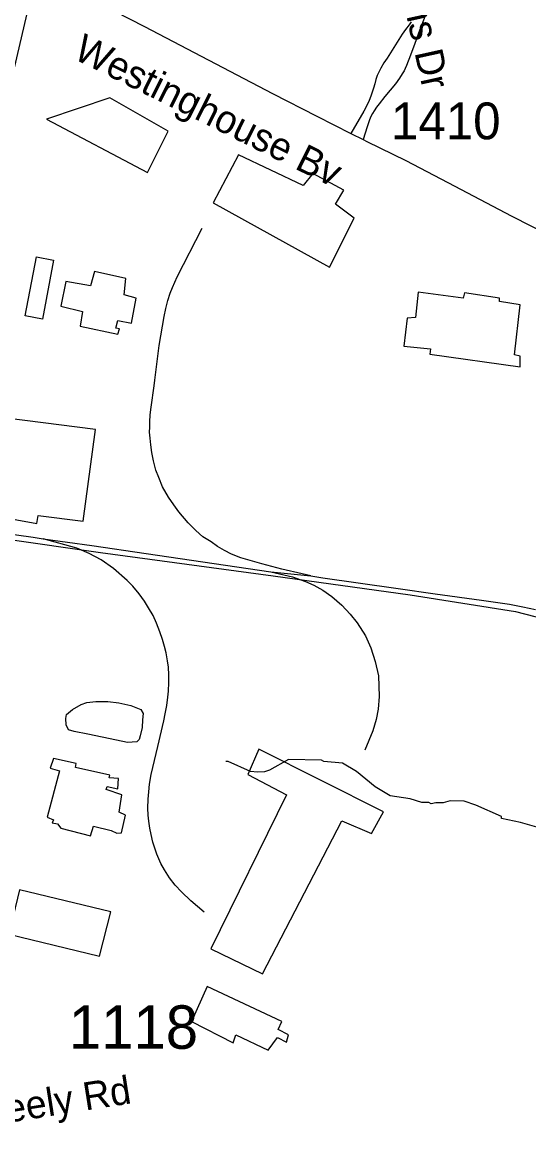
# Model space of a CAD drawing. Extents: x 1383679 to 1536984, y 460658 to 651027.
# Drawn here: x 1408689 to 1410408, y 506502 to 510300 of the extents above; entities that cross this region are included whole.
import ezdxf

# ---------------------------------------------------------------- set-up
doc = ezdxf.new("R2010")
doc.units = 0
for name, color, linetype in [('Exist Cultural Warehouse Building Footprint', 7, 'Continuous'), ('Exist Hydrographic Misc Water Feature', 7, 'Continuous'), ('Exist Railroad Mainline', 7, 'Continuous'), ('Exist Railroad Spur', 7, 'Continuous'), ('Exist Road Non-System Secondary Historical Number Label', 7, 'Continuous'), ('Exist Road Non-System Type 51', 7, 'Continuous'), ('Exist Road Non-System Type 51 Label', 7, 'Continuous'), ('Exist Road Primary NC Attributed', 7, 'Continuous'), ('Exist Road Secondary Type 51 Attributed', 7, 'Continuous'), ('Exist Road Secondary Type 51 Label', 7, 'Continuous'), ('Exist Road Secondary Type 51 Number Label', 7, 'Continuous')]:
    doc.layers.add(name, color=color, linetype=linetype)

msp = doc.modelspace()

# ---------------------------------------------------------------- linework, layer by layer
at = {"layer": 'Exist Cultural Warehouse Building Footprint'}
for points in [[(1408985.1, 510044.1), (1408769.9, 509971.5), (1409113.7, 509790), (1409183.8, 509930.7), (1408985.1, 510044.1)], [(1409422.4, 509850.1), (1409335.9, 509686.8), (1409731.1, 509469), (1409815.3, 509634.6), (1409752.1, 509682.2), (1409780.2, 509729.9), (1409674.9, 509786.6), (1409642.2, 509745.8), (1409422.4, 509850.1)], [(1408736.2, 509503.7), (1408794.5, 509492.7), (1408756.6, 509292.4), (1408698.3, 509303.4), (1408736.2, 509503.7)], [(1408836.5, 509420.1), (1408819.3, 509336.5), (1408893, 509318.2), (1408885.1, 509268), (1409012.1, 509240.7), (1409018.3, 509258.9), (1409005.8, 509262), (1409012.1, 509287.8), (1409059.1, 509278.7), (1409074.7, 509363.8), (1409034, 509374.5), (1409040.3, 509430.7), (1408933.7, 509453.5), (1408919.6, 509404.9), (1408836.5, 509420.1)], [(1410032.7, 509383.9), (1410023.4, 509297.7), (1409995.3, 509295.4), (1409983.6, 509200.1), (1410074.8, 509191.1), (1410072.5, 509172.9), (1410378.9, 509129.8), (1410378.9, 509166.1), (1410360.1, 509170.7), (1410378.9, 509340.8), (1410308.7, 509352.1), (1410308.7, 509363.5), (1410189.4, 509381.6), (1410184.8, 509363.5), (1410032.7, 509383.9)], [(1408518.4, 508970.8), (1408505.9, 508882.7), (1408452.6, 508887.2), (1408436.9, 508785.4), (1408487.1, 508771.7), (1408477.7, 508645.5), (1408737.8, 508598.4), (1408742.5, 508625.7), (1408894.5, 508606), (1408936.8, 508917.6), (1408518.4, 508970.8)], [(1409328.6, 507153.4), (1409504.1, 507068.3), (1409773.7, 507588.2), (1409874, 507545.6), (1409914.7, 507618.6), (1409491.6, 507831.4), (1409454, 507746.3), (1409585.6, 507676.4), (1409328.6, 507153.4)], [(1408794.2, 507800.3), (1408783.3, 507766.8), (1408814.6, 507757.7), (1408772.3, 507601.1), (1408794.2, 507592), (1408789.5, 507581.3), (1408808.3, 507578.3), (1408819.3, 507563.1), (1408919.6, 507537.3), (1408930.6, 507570.7), (1408990.1, 507555.5), (1409008.9, 507546.4), (1409024.6, 507547.9), (1409038.7, 507607.2), (1409016.8, 507617.8), (1409026.2, 507677.1), (1408972.9, 507695.4), (1408976, 507704.5), (1409012.1, 507696.9), (1409015.2, 507731.8), (1408983.8, 507734.9), (1408985.4, 507744), (1408869.4, 507769.8), (1408871, 507783.5), (1408794.2, 507800.3)], [(1408678.3, 507354.1), (1408642.2, 507203.6), (1408950.9, 507129.1), (1408988.5, 507279.6), (1408678.3, 507354.1)], [(1409316.1, 507025.7), (1409262.8, 506907.1), (1409403.8, 506834.1), (1409413.2, 506861.5), (1409522.9, 506809.8), (1409554.3, 506852.4), (1409585.6, 506837.2), (1409591.9, 506861.5), (1409557.4, 506879.7), (1409569.9, 506907.1), (1409316.1, 507025.7)]]:
    msp.add_lwpolyline(points, dxfattribs=at)
at = {"layer": 'Exist Hydrographic Misc Water Feature'}
for points in [[(1408836.2, 507935.7), (1408838.5, 507949.9), (1408858.5, 507966.2), (1408887.8, 507983.5), (1408907.6, 507990.2), (1408938, 507994.2), (1408978.7, 507994), (1409016.4, 507989.3), (1409056.3, 507980.6), (1409091, 507967), (1409098.5, 507952.9), (1409096.7, 507931.5), (1409095.1, 507905.2), (1409088.1, 507877.5), (1409085.6, 507864.3), (1409076.9, 507857.1), (1409045.8, 507854.5), (1409008.1, 507862.4), (1408959.4, 507872.4), (1408910.7, 507882.7), (1408864.5, 507891.6), (1408845.7, 507898), (1408836.8, 507914.3), (1408836.2, 507935.7)], [(1410482.7, 507553), (1410379.9, 507583.1), (1410315.7, 507596.7), (1410315.8, 507602.7), (1410228.4, 507642), (1410188.9, 507655.6), (1410140.9, 507656.7), (1410116.8, 507649.2), (1410092.8, 507649.7), (1410076.7, 507646.1), (1410068.8, 507650.3), (1410044.9, 507650.8), (1410005.1, 507663.7), (1409937.3, 507673.2), (1409885.9, 507704.1), (1409823, 507755.8), (1409775.6, 507784.8), (1409711.7, 507790.3), (1409703.9, 507794.4), (1409591.9, 507796.9), (1409527.1, 507760.4), (1409511, 507754.8), (1409486.9, 507753.4), (1409462.9, 507755.9), (1409387.7, 507789.5), (1409379.7, 507789.7)]]:
    msp.add_lwpolyline(points, dxfattribs=at)
at = {"layer": 'Exist Railroad Mainline'}
for p, q in [((1409108.5, 508496.5), (1409532.4, 508434.5)), ((1409532.4, 508434.5), (1409667.9, 508421))]:
    msp.add_line(p, q, dxfattribs=at)
for points in [[(1407534.2, 508716.7), (1407546.9, 508714.9), (1408075, 508641.5), (1408209.8, 508624.1), (1408355.7, 508603.6), (1408506.9, 508582), (1408619.9, 508566.4), (1408724.7, 508551.7), (1408759.1, 508546.4)], [(1408759.1, 508546.4), (1408924, 508523.5), (1409108.5, 508496.5)], [(1409667.9, 508421), (1409708.4, 508413.9), (1409828.6, 508396.8), (1409964.7, 508377.9), (1410090.3, 508359.8), (1410247, 508338.1), (1410342.4, 508324.7), (1410387.4, 508315.7), (1410430.8, 508305.7)]]:
    msp.add_lwpolyline(points, dxfattribs=at)
at = {"layer": 'Exist Railroad Spur'}
for points in [[(1409667.9, 508421), (1409638.7, 508427.3), (1409569.2, 508443.3), (1409501.5, 508460.7), (1409429.9, 508481.4), (1409399.1, 508494.1), (1409375.1, 508506.5), (1409351.5, 508520.4), (1409329.5, 508536.2), (1409301.4, 508553.1), (1409277.1, 508574.6), (1409251.3, 508600.5), (1409220, 508637.9), (1409202.9, 508661.6), (1409184.5, 508687.9), (1409164.1, 508722.9), (1409151.4, 508754.5), (1409142, 508779), (1409134.2, 508810.8), (1409128.6, 508839), (1409124.3, 508865.8), (1409122, 508887.6), (1409120.7, 508908.1), (1409120.8, 508924.8), (1409121.1, 508943.9), (1409122, 508966.7), (1409125.9, 508993.6), (1409135.5, 509066), (1409138, 509085.2), (1409153.5, 509202.3), (1409169.7, 509301), (1409175.7, 509327.9), (1409183, 509355.3), (1409190.8, 509379.9), (1409198.6, 509399.1), (1409213.8, 509436.3), (1409298.5, 509601)], [(1409305.8, 507278), (1409260.6, 507317.1), (1409229.3, 507347.5), (1409207.5, 507369.9), (1409188.3, 507394.3), (1409171, 507421.5), (1409159.2, 507443.8), (1409145.5, 507475), (1409138, 507495.5), (1409131.7, 507515.7), (1409125.3, 507542.2), (1409121, 507563.4), (1409117.6, 507587.8), (1409115.8, 507607.6), (1409115, 507631.9), (1409116.1, 507661.8), (1409117.6, 507687.2), (1409120.3, 507712.7), (1409125.8, 507746), (1409148.2, 507841.2), (1409168.3, 507927.7), (1409173.8, 507952.2), (1409178.7, 507980), (1409182.5, 508008.8), (1409184.6, 508028.7), (1409185.5, 508057.8), (1409185.5, 508084.6), (1409184.3, 508110.7), (1409181.3, 508132.2), (1409176.6, 508159), (1409171.5, 508180.1), (1409164.7, 508204.5), (1409155.7, 508230.5), (1409143.8, 508260.1), (1409132.4, 508285.3), (1409116.9, 508312.3), (1409102.9, 508334.2), (1409085.2, 508359.6), (1409063.2, 508385.6), (1409044.6, 508404.2), (1408998, 508445.6), (1408956.3, 508475), (1408915.8, 508496.5), (1408873.4, 508514.2), (1408759.1, 508546.4)], [(1409532.4, 508434.5), (1409605.3, 508416.9), (1409649.4, 508401.6), (1409678, 508389.3), (1409708.4, 508371.7), (1409739.2, 508350.2), (1409773.3, 508320.6), (1409802, 508290.7), (1409825.3, 508260.7), (1409853.4, 508217.2), (1409872, 508175.9), (1409887, 508129), (1409897.2, 508080.5), (1409900.5, 508010.7), (1409896.7, 507967.4), (1409889.5, 507932.9), (1409878.7, 507894.5), (1409851.2, 507828.3)]]:
    msp.add_lwpolyline(points, dxfattribs=at)
at = {"layer": 'Exist Road Non-System Type 51'}
for points in [[(1410064, 510342.8), (1410036.9, 510272.5), (1410021.7, 510227.9), (1410006.6, 510189.1), (1409992.9, 510153.9), (1409988.3, 510143.2), (1409984.6, 510135.5), (1409978.5, 510124.8), (1409968.6, 510110), (1409955.6, 510091.8), (1409919.4, 510048.8), (1409900, 510023.5), (1409891.4, 510011.7), (1409883.5, 509999.6), (1409877.8, 509990.2), (1409870.8, 509977.7), (1409865.9, 509965.7), (1409859.7, 509944.8), (1409845.2, 509902.2)], [(1410008.6, 510302.2), (1410002, 510291.2), (1409989.9, 510276.2), (1409978.5, 510260.4), (1409927, 510178.9), (1409916.3, 510162.3), (1409905.9, 510144.5), (1409898.5, 510131.1), (1409893.4, 510119.3), (1409889.2, 510106.3), (1409885.3, 510091.3), (1409880.9, 510076.6), (1409876.5, 510062.5), (1409871.9, 510049.6), (1409865.9, 510034.6), (1409857.6, 510017.3), (1409847.5, 509998.5), (1409803.9, 509923.2)], [(1408297.7, 508594), (1408953.6, 508500.2), (1409539.6, 508419.9), (1410005, 508356.4), (1410363.5, 508299.5), (1410529, 508256)]]:
    msp.add_lwpolyline(points, dxfattribs=at)
at = {"layer": 'Exist Road Primary NC Attributed'}
msp.add_lwpolyline([(1408075.2, 507636.1), (1408736.5, 510466.6)], dxfattribs=at)
at = {"layer": 'Exist Road Secondary Type 51 Attributed'}
msp.add_lwpolyline([(1409001.6, 510337.7), (1409103.7, 510285.7), (1409538, 510058.9), (1409688.4, 509981.9), (1409803.9, 509923.2), (1409845.2, 509902.2), (1409858, 509895.7), (1409990.7, 509830.9), (1410157.2, 509743.5), (1410348.4, 509642.8), (1410619.6, 509504.4)], dxfattribs=at)

# ---------------------------------------------------------------- texts
at = {"layer": 'Exist Road Non-System Secondary Historical Number Label'}
msp.add_text('1118', height=147.64, dxfattribs=at).set_placement((1408846, 506814.2))
at = {"layer": 'Exist Road Non-System Type 51 Label'}
for s, rotation, p in [('Westinghouse Commons Dr', 282.4415, (1409706.3, 511618.6)), ('Sam Neely Rd', 8.9694, (1408253.6, 506502))]:
    msp.add_text(s, height=95, rotation=rotation, dxfattribs=at).set_placement(p)
at = {"layer": 'Exist Road Secondary Type 51 Label'}
msp.add_text('Westinghouse Bv', height=95, rotation=333.5755, dxfattribs=at).set_placement((1408857.3, 510179))
at = {"layer": 'Exist Road Secondary Type 51 Number Label'}
msp.add_text('1410', height=125, dxfattribs=at).set_placement((1409940.4, 509903))

doc.saveas('drawing.dxf')
